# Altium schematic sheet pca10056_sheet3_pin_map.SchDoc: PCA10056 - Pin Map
size A3; Organization: Nordic Semiconductor; DocumentNumber: 3; SheetNumber: 3; SheetTotal: 7; CompanyName: Nordic Semiconductor
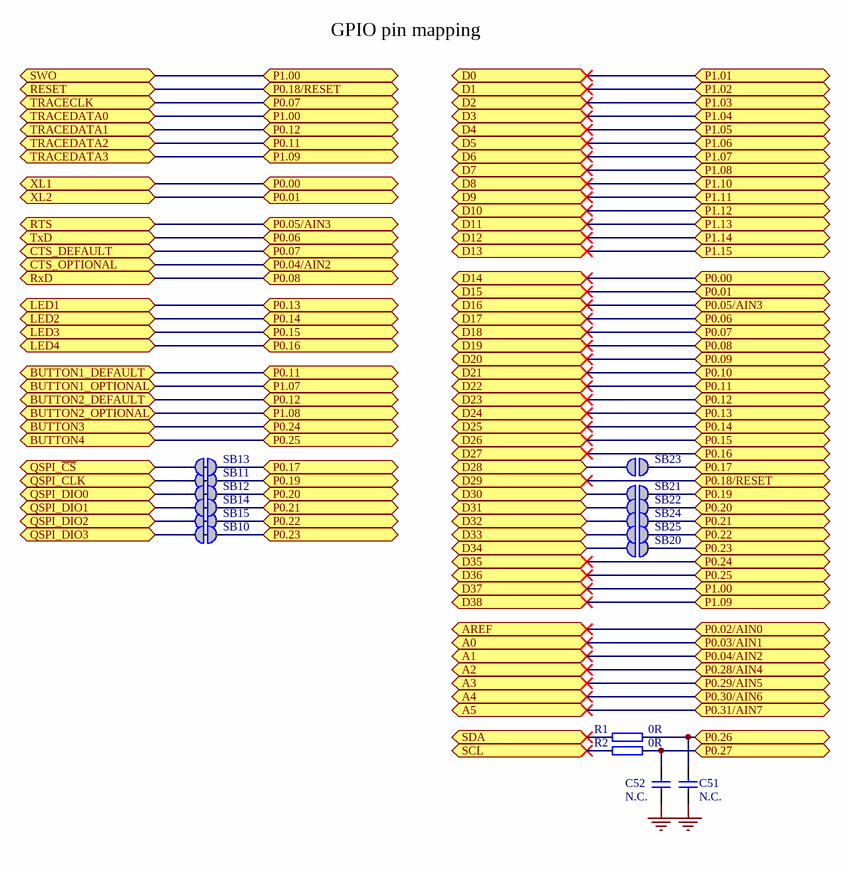
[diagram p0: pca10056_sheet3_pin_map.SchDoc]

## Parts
C51  N.C.  [CAPC1005X04L]
C52  N.C.  [CAPC1005X04L]
R1  0R  [RESC1005X04L]
R2  0R  [RESC1005X04L]
SB10  Solderbridge  [Solderbridge_Shorted]  (value not drawn)  (net tie, no BOM)
SB11  Solderbridge  [Solderbridge_Shorted]  (value not drawn)  (net tie, no BOM)
SB12  Solderbridge  [Solderbridge_Shorted]  (value not drawn)  (net tie, no BOM)
SB13  Solderbridge  [Solderbridge_Shorted]  (value not drawn)  (net tie, no BOM)
SB14  Solderbridge  [Solderbridge_Shorted]  (value not drawn)  (net tie, no BOM)
SB15  Solderbridge  [Solderbridge_Shorted]  (value not drawn)  (net tie, no BOM)
SB20  Solderbridge  [Solderbridge]  (value not drawn)  (no BOM)
SB21  Solderbridge  [Solderbridge]  (value not drawn)  (no BOM)
SB22  Solderbridge  [Solderbridge]  (value not drawn)  (no BOM)
SB23  Solderbridge  [Solderbridge]  (value not drawn)  (no BOM)
SB24  Solderbridge  [Solderbridge]  (value not drawn)  (no BOM)
SB25  Solderbridge  [Solderbridge]  (value not drawn)  (no BOM)

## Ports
A0 (bidir), A1 (bidir), A2 (bidir), A3 (bidir), A4 (bidir), A5 (bidir), AREF (bidir), BUTTON1_DEFAULT (bidir), BUTTON1_OPTIONAL (bidir), BUTTON2_DEFAULT (bidir), BUTTON2_OPTIONAL (bidir), BUTTON3 (bidir), BUTTON4 (bidir), CTS_DEFAULT (bidir), CTS_OPTIONAL (bidir), D0 (bidir), D1 (bidir), D2 (bidir), D3 (bidir), D4 (bidir), D5 (bidir), D6 (bidir), D7 (bidir), D8 (bidir), D9 (bidir), D10 (bidir), D11 (bidir), D12 (bidir), D13 (bidir), D14 (bidir), D15 (bidir), D16 (bidir), D17 (bidir), D18 (bidir), D19 (bidir), D20 (bidir), D21 (bidir), D22 (bidir), D23 (bidir), D24 (bidir), D25 (bidir), D26 (bidir), D27 (bidir), D28 (bidir), D29 (bidir), D30 (bidir), D31 (bidir), D32 (bidir), D33 (bidir), D34 (bidir), D35 (bidir), D36 (bidir), D37 (bidir), D38 (bidir), LED1 (bidir), LED2 (bidir), LED3 (bidir), LED4 (bidir), P0.00 (bidir), P0.01 (bidir), P0.02/AIN0 (bidir), P0.03/AIN1 (bidir), P0.04/AIN2 (bidir), P0.05/AIN3 (bidir), P0.06 (bidir), P0.07 (bidir), P0.08 (bidir), P0.09 (bidir), P0.10 (bidir), P0.11 (bidir), P0.12 (bidir), P0.13 (bidir), P0.14 (bidir), P0.15 (bidir), P0.16 (bidir), P0.17 (bidir), P0.18/RESET (bidir), P0.19 (bidir), P0.20 (bidir), P0.21 (bidir), P0.22 (bidir), P0.23 (bidir), P0.24 (bidir), P0.25 (bidir), P0.26 (bidir), P0.27 (bidir), P0.28/AIN4 (bidir), P0.29/AIN5 (bidir), P0.30/AIN6 (bidir), P0.31/AIN7 (bidir), P1.00 (bidir), P1.01 (bidir), P1.02 (bidir), P1.03 (bidir), P1.04 (bidir), P1.05 (bidir), P1.06 (bidir), P1.07 (bidir), P1.08 (bidir), P1.09 (bidir), P1.10 (bidir), P1.11 (bidir), P1.12 (bidir), P1.13 (bidir), P1.14 (bidir), P1.15 (bidir), QSPI_CLK (bidir), QSPI_DIO0 (bidir), QSPI_DIO1 (bidir), QSPI_DIO2 (bidir), QSPI_DIO3 (bidir), QSPI_~{CS} (bidir), RESET (bidir), RTS (bidir), RxD (bidir), SCL (bidir), SDA (bidir), SWO (bidir), TRACECLK (bidir), TRACEDATA0 (bidir), TRACEDATA1 (bidir), TRACEDATA2 (bidir), TRACEDATA3 (bidir), TxD (bidir), XL1 (bidir), XL2 (bidir)

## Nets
GND: C51.1 C52.2
A0: port A0, port P0.03/AIN1
A1: port P0.04/AIN2, port CTS_OPTIONAL, port A1
A2: port A2, port P0.28/AIN4
A3: port A3, port P0.29/AIN5
A4: port A4, port P0.30/AIN6
A5: port A5, port P0.31/AIN7
AREF: port AREF, port P0.02/AIN0
BUTTON1_DEFAULT: port TRACEDATA2, port P0.11, port BUTTON1_DEFAULT, port D22
BUTTON1_OPTIONAL: port P1.07, port BUTTON1_OPTIONAL, port D6
BUTTON2_DEFAULT: port TRACEDATA1, port P0.12, port BUTTON2_DEFAULT, port D23
BUTTON2_OPTIONAL: port P1.08, port BUTTON2_OPTIONAL, port D7
BUTTON3: port P0.24, port BUTTON3, port D35
BUTTON4: port P0.25, port BUTTON4, port D36
CTS_DEFAULT: port P0.07, port TRACECLK, port CTS_DEFAULT, port D18
D0: port P1.01, port D0
D1: port P1.02, port D1
D2: port P1.03, port D2
D3: port P1.04, port D3
D4: port P1.05, port D4
D5: port P1.06, port D5
D8: port P1.10, port D8
D9: port P1.11, port D9
D10: port P1.12, port D10
D11: port P1.13, port D11
D12: port P1.14, port D12
D13: port P1.15, port D13
D14: port P0.00, port XL1, port D14
D15: port P0.01, port XL2, port D15
D16: port RTS, port D16, port P0.05/AIN3
D17: port TxD, port P0.06, port D17
D19: port RxD, port P0.08, port D19
D20: port D20, port P0.09
D21: port D21, port P0.10
D24: port P0.13, port LED1, port D24
D25: port P0.14, port LED2, port D25
D26: port P0.15, port LED3, port D26
D27: port P0.16, port LED4, port D27
D28: SB23.2 ; port D28
D29: port RESET, port P0.18/RESET, port D29
D30: SB21.2 ; port D30
D31: SB22.2 ; port D31
D32: SB24.2 ; port D32
D33: SB25.2 ; port D33
D34: SB20.2 ; port D34
D37: port TRACEDATA0, port SWO, port P1.00, port D37
D38: port TRACEDATA3, port P1.09, port D38
P0.17: SB13.1 SB23.1 ; port P0.17
P0.19: SB11.1 SB21.1 ; port P0.19
P0.20: SB12.1 SB22.1 ; port P0.20
P0.21: SB14.1 SB24.1 ; port P0.21
P0.22: SB15.1 SB25.1 ; port P0.22
P0.23: SB10.1 SB20.1 ; port P0.23
P0.26: C51.2 R1.2 ; port P0.26
P0.27: C52.1 R2.2 ; port P0.27
QSPI_~{CS}: SB13.2 ; port QSPI_~{CS}
QSPI_CLK: SB11.2 ; port QSPI_CLK
QSPI_DIO0: SB12.2 ; port QSPI_DIO0
QSPI_DIO1: SB14.2 ; port QSPI_DIO1
QSPI_DIO2: SB15.2 ; port QSPI_DIO2
QSPI_DIO3: SB10.2 ; port QSPI_DIO3
SCL: R2.1 ; port SCL
SDA: R1.1 ; port SDA

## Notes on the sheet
- GPIO pin mapping

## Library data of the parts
C51 C52 = C0402-N.C.: Not mounted; Assembly: Not mounted; Note: Chip Cap; Artikkelnr Noca: N.A.
R1 R2 = R0402-0R: Resistor, ±5%, 0.063W; Note: Chip Res 5%; Artikkelnr Noca: 27049000; Artikkelnr Simpro: N.A.; Value Ohm: 0
SB10-SB15 = Solderbridge Shorted: Shorted Solderbridge; Artikkelnr Noca: N.A.
SB20-SB25 = Solderbridge: Artikkelnr Noca: N.A.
